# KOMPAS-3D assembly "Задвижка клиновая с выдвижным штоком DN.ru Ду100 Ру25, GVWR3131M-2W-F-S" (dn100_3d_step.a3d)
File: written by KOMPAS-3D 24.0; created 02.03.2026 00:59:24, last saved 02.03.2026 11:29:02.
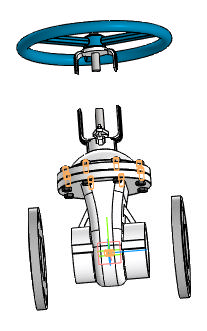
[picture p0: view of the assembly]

Document properties: Автор: R2D2; Полное имя файла: E:\Работа\Зайцев\GVWR3131M-2W-F-S Задвижка клиновая 30нж64нж DN.ru  Ду50-150 Ру25\исходные данные\DN100\dn100_3d_step.a3d

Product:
- Component [detail]: Деталь2  | qty 1  | pos. 1  | Масса: 5.406695; Автор: R2D2; additional columns: Типовые; source file: Деталь2 Деталь2.m3d
- Component [detail]: ANSI B18.2.4.2M - M5x0,8 - 8  | designation ANSI B18.2.4.2M - M5x0,8  | qty 2  | pos. 2  | Масса: 0.00167; Комментарий: Типы метрических   шестигранных гаек   2; Автор: R2D2; additional columns: Сталь, мягкая; source file: ANSI B18.2.4.2M - M5x0,8 ANSI B18.2.4.2M - M5x0,8 - 8.m3d
- Component [detail]: Деталь1  | qty 1  | pos. 3  | Масса: 36.799325; additional columns: Типовые; source file: 2.m3d
- Component [detail]: Деталь1  | qty 1  | pos. 3  | Масса: 0.571095; Автор: R2D2; additional columns: Типовые; source file: 3.m3d
- Component [detail]: Деталь1  | qty 2  | pos. 3  | Масса: 5.317036; Автор: R2D2; additional columns: Типовые; source file: 1.m3d
- Component [standard]: Болт М12-6gx50.88.45Г.019 ГОСТ 7798-70  | qty 8  | Материал: Сталь 45Г (density 7850 kg/m3); Масса: 0.06053; Раздел спецификации: Стандартные изделия; Рассекать на разрезах: no; additional columns: BOSimple***Material:39848d99-529e-4aa2-825c-393daa009d15
- Component [standard]: Гайка М12-6H ГОСТ 5915-70  | qty 24  | Масса: 0.0184; Раздел спецификации: Стандартные изделия; Рассекать на разрезах: no
- Part/product: Задвижка клиновая с выдвижным штоком DN.ru Ду100 Ру25  | designation GVWR3131M-2W-F-S
    Масса: 29
    Раздел спецификации: Прочие изделия
    Примечание: D040-07876

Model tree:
1. Массив по концентрической сетке:1  (labels: Грань.Твердое тело1)  (8 pattern instances)
     Шаг 2 = 360
2. Массив по концентрической сетке:2  (with: Грань.Элемент вращения:1)  (labels: Грань.Твердое тело1; Грань.Solid1)  (2 pattern instances)
     Шаг 2 = 360; Расстояние = -525; Расстояние = -175; Ориентация = 2

Referenced files in E:\Работа\Зайцев\GVWR3131M-2W-F-S Задвижка клиновая 30нж64нж DN.ru  Ду50-150 Ру25\исходные данные\DN100\: Деталь2 Деталь2.m3d, ANSI B18.2.4.2M - M5x0,8 ANSI B18.2.4.2M - M5x0,8 - 8.m3d, 2.m3d, 3.m3d, 1.m3d
Referenced files in C:\Program Files\ASCON\KOMPAS-3D v24\Libs\PolynomLib\DATA\vault\Methods\Kompas\3D\: PLib_Bolt_1_900.m3d, PLib_Nut_OST92_900.m3d
Referenced files in E:\Работа\Зайцев\GVWR3131M-2W-F-S Задвижка клиновая с выдвижным штоком DN.ru Ду50-200 Ру63\DN100\исходные материалы\: 1.m3d, ANSI B18.2.4.2M - M5x0,8 ANSI B18.2.4.2M - M5x0,8 - 8.m3d
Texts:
  ANSI B18.2.4.2M - M5x0,8
  Крепежное изделие ГОСТ
  BOSimple***PART:25ccc031-f2ed-a43b-e633-090566d53ffa***SHORTLOC:Root±30±20±10±80±10±©{}30±©{BASE}130±290[9;Цинковое, хроматированное;Сталь 45Г ГОСТ 4543-2016;50;12;19;1,75;8.8]
  BOSimple***Material:39848d99-529e-4aa2-825c-393daa009d15
  BOSimple***PART:dfaf85ed-3e43-003f-b29c-9c5b054070d3***SHORTLOC:Root±30±10±20±©{}110±10±50±60[Нет;Без покрытия;Без указания материала;-;12;1,75;19]
  Программные изделия  и базы данных
  GVWR3131M-2W-F-S
  Деталь2 Деталь2
  ANSI B18.2.4.2M - M5x0,8 ANSI B18.2.4.2M - M5x0,8 - 8 (1)
  Деталь1 Деталь1
  Деталь1 Деталь1 (1)
  Деталь1 Деталь1 (2)
  Болт М12-6gx50.88.45Г.019 ГОСТ 7798-70 (1)
  hole1
  hole2
  Гайка М12-6H ГОСТ 5915-70 (1)
  bcut1
  hcut1
  cut1
  Гайка М12-6H ГОСТ 5915-70 (2)
  Гайка М12-6H ГОСТ 5915-70 (3)
  Ось Z.Начало координат
  Ось Y.Начало координат
  Плоскость ZX.Начало координат
  Плоскость XY.Начало координат
  Plane. Начало координат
